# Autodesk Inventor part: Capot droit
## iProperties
Created: 2001-06
Part Number: Capot droit
Material: Par défaut
Document SubType Name: Modélisation
Designer: Flavien MARTY
Control State: 0
Master: False
Checked Out: False
Shininess: 20.0
Length Units: 11269
Angle Units: 11279
Time Units: 11290
Mass Units: 11283
Length Display Precision: 3
Angle Display Precision: 2
Compacted: True
Density: 0.0
Volumn: 0.0
Area: 0.0
PropertySet Name: Model Information
Author: Flavien MARTY
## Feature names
1. Extrusion1
2. Extrusion2
3. Extrusion3
4. Perçage1 [Hole]
5. Extrusion4
6. Extrusion5
7. Perçage2 [Hole]
8. Base Pion [Extrusion]
9. Pion [Extrusion]
10. Extrusion8
11. Extrusion9
12. Perçage3 [Hole]
13. Extrusion10
14. Extrusion11
15. Extrusion12
16. Perçage4 [Hole]
17. Extrusion14
18. Extrusion15
19. Extrusion16
20. Chanfrein1 [Chamfer]
21. Extrusion17
22. Extrusion18
23. Extrusion19
24. Extrusion20
25. Extrusion21
26. Extrusion22
27. Extrusion23
28. Symétrie1 [Mirror]
29. Extrusion24
30. Extrusion25
31. Extrusion26
32. Extrusion27
33. Passage essieu [Extrusion]
34. Perçage5 [Hole]
35. Extrusion29
36. Extrusion30
37. Extrusion31
38. Congé1 [Fillet]
39. Extrusion32
40. Congé2 [Fillet]
41. Extrusion33
42. Extrusion34
43. Extrusion37
44. Extrusion36
45. Extrusion38
46. Extrusion39
47. Perçage6 [Hole]
48. Extrusion40
49. Extrusion41
50. Extrusion42
51. Extrusion43
52. Perçage7 [Hole]
53. Perçage8 [Hole]
54. Perçage9 [Hole]
55. Perçage10 [Hole]
56. Perçage11 [Hole]
57. Perçage12 [Hole]
58. Extrusion44
59. Extrusion45
60. Extrusion46
61. Extrusion47
